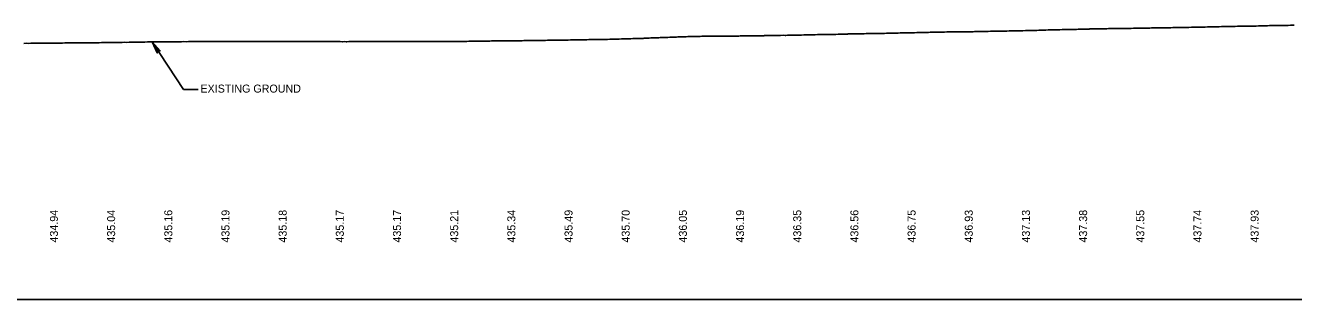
# Model space of a CAD drawing. Extents: x 2017200 to 2047700, y 854850 to 893350.
# Drawn here: x 2021520 to 2022630, y 856100 to 856340 of the extents above; entities that cross this region are included whole.
import ezdxf

# ---------------------------------------------------------------- set-up
doc = ezdxf.new("R2010")
doc.units = 0
for name, color, linetype in [('RD_DDB_Profile_EX', 7, 'Continuous'), ('RD_DDB_Profile_Lbl', 7, 'Continuous'), ('RD_DDB_StripGrade', 7, 'Continuous'), ('RD_GPK_Profile_Cell', 7, 'Continuous')]:
    doc.layers.add(name, color=color, linetype=linetype)

msp = doc.modelspace()

# ---------------------------------------------------------------- linework, layer by layer
at = {"layer": 'RD_DDB_Profile_EX'}
msp.add_lwpolyline([(2021519.1, 856324.3), (2021521.2, 856324.5), (2021523.1, 856324.4), (2021525.3, 856324.5), (2021527.1, 856324.5), (2021529.1, 856324.5), (2021531.1, 856324.5), (2021533.1, 856324.5), (2021533.7, 856324.5), (2021535.1, 856324.6), (2021537.1, 856324.5), (2021539.1, 856324.6), (2021541.1, 856324.6), (2021543.1, 856324.6), (2021545.1, 856324.6), (2021547.2, 856324.7), (2021549.1, 856324.7), (2021551.1, 856324.7), (2021553.1, 856324.7), (2021555.1, 856324.8), (2021555.7, 856324.8), (2021557.1, 856324.8), (2021559.1, 856324.8), (2021561.1, 856324.8), (2021563.1, 856324.9), (2021565.1, 856324.9), (2021567.2, 856324.9), (2021569.1, 856324.9), (2021571.1, 856324.9), (2021573.1, 856324.9), (2021573.9, 856324.9), (2021575.1, 856324.9), (2021577.1, 856325), (2021579.1, 856325), (2021581.1, 856325), (2021583.1, 856325), (2021585.1, 856325), (2021587.1, 856325.1), (2021589.1, 856325.1), (2021591.1, 856325.1), (2021593.1, 856325.1), (2021595.1, 856325.1), (2021597.1, 856325.2), (2021599.1, 856325.2), (2021600.2, 856325.2), (2021601.1, 856325.2), (2021603.1, 856325.2), (2021605.1, 856325.2), (2021607.1, 856325.3), (2021609.1, 856325.2), (2021611.2, 856325.3), (2021613.1, 856325.3), (2021615.3, 856325.3), (2021617.1, 856325.4), (2021619.1, 856325.4), (2021621.3, 856325.5), (2021623.1, 856325.5), (2021625.1, 856325.5), (2021627.2, 856325.6), (2021629.1, 856325.6), (2021631.3, 856325.6), (2021633.2, 856325.7), (2021635.2, 856325.7), (2021637.3, 856325.7), (2021639.2, 856325.7), (2021641.2, 856325.7), (2021641.6, 856325.7), (2021643.1, 856325.8), (2021644.5, 856325.8), (2021645.1, 856325.8), (2021647.1, 856325.8), (2021647.5, 856325.8), (2021649.1, 856325.8), (2021651.1, 856325.8), (2021652.9, 856325.8), (2021653.2, 856325.8), (2021654.8, 856325.8), (2021655.2, 856325.8), (2021657.1, 856325.8), (2021659.2, 856325.9), (2021661.2, 856325.8), (2021663.3, 856325.9), (2021665.2, 856325.9), (2021667.1, 856325.9), (2021669.2, 856325.9), (2021671.1, 856325.9), (2021673.2, 856325.9), (2021675.1, 856325.9), (2021677.1, 856325.9), (2021679.1, 856325.9), (2021681.1, 856325.9), (2021683.1, 856325.9), (2021683.6, 856325.9), (2021685.1, 856325.9), (2021687.1, 856325.9), (2021689.1, 856325.9), (2021691.1, 856326), (2021693.1, 856325.9), (2021695.1, 856325.9), (2021697.1, 856325.9), (2021698.4, 856325.9), (2021699.1, 856325.9), (2021701.1, 856325.9), (2021703.1, 856325.9), (2021705.1, 856326), (2021707.1, 856325.9), (2021709.1, 856325.9), (2021709.5, 856325.9), (2021711.1, 856325.9), (2021713.2, 856325.9), (2021715.2, 856325.9), (2021717.2, 856325.9), (2021719.1, 856325.9), (2021721.1, 856325.9), (2021723.2, 856325.9), (2021725.2, 856325.9), (2021726.7, 856325.9), (2021727.2, 856325.9), (2021729.3, 856325.9), (2021730.9, 856325.9), (2021731.2, 856325.9), (2021733.3, 856325.9), (2021735, 856325.9), (2021735.5, 856325.9), (2021736.8, 856325.9), (2021737.3, 856325.9), (2021739.1, 856325.9), (2021739.5, 856325.9), (2021741, 856325.9), (2021742.6, 856325.9), (2021743.4, 856325.9), (2021745.1, 856325.9), (2021746.8, 856325.9), (2021747.2, 856325.9), (2021749.2, 856325.9), (2021751.2, 856325.9), (2021752.7, 856325.9), (2021753.2, 856325.9), (2021755.2, 856325.9), (2021756.9, 856325.9), (2021757.2, 856325.9), (2021759.3, 856325.9), (2021761, 856325.9), (2021761.4, 856325.9), (2021763.3, 856325.9), (2021764.4, 856325.9), (2021765.1, 856325.9), (2021765.4, 856325.9), (2021767.1, 856325.9), (2021768.7, 856325.9), (2021769.5, 856325.9), (2021771.2, 856325.9), (2021771.8, 856325.9), (2021772.2, 856325.9), (2021773.2, 856325.9), (2021774.5, 856325.9), (2021775.3, 856325.9), (2021777.3, 856325.9), (2021778.9, 856325.9), (2021779.4, 856325.9), (2021780, 856325.9), (2021781.4, 856325.9), (2021783.1, 856325.9), (2021783.5, 856325.9), (2021784.8, 856325.9), (2021785.5, 856325.9), (2021787.2, 856325.9), (2021787.8, 856325.9), (2021789.2, 856325.9), (2021789.5, 856325.9), (2021791.6, 856325.9), (2021793.3, 856325.9), (2021793.9, 856325.9), (2021795.7, 856325.9), (2021797.4, 856325.8), (2021797.8, 856325.8), (2021799.4, 856325.9), (2021801, 856325.8), (2021801.5, 856325.8), (2021803.5, 856325.9), (2021805.6, 856325.9), (2021807, 856325.9), (2021807.6, 856325.9), (2021809.6, 856325.9), (2021811.3, 856325.9), (2021811.6, 856325.9), (2021813.7, 856325.9), (2021815.7, 856325.9), (2021817.7, 856325.9), (2021819, 856325.9), (2021819.8, 856325.9), (2021821.7, 856325.9), (2021823.8, 856325.9), (2021825.7, 856325.9), (2021826.8, 856325.9), (2021827.7, 856325.9), (2021829.7, 856325.9), (2021831.7, 856325.9), (2021833.8, 856325.9), (2021834.6, 856325.9), (2021835.3, 856325.9), (2021835.8, 856325.9), (2021837.8, 856325.9), (2021839.9, 856325.9), (2021841.8, 856325.9), (2021842.4, 856325.9), (2021843.9, 856325.9), (2021845.9, 856325.9), (2021847.9, 856325.9), (2021850.2, 856325.9), (2021852, 856325.9), (2021854, 856325.9), (2021856.1, 856325.9), (2021858, 856325.9), (2021860, 856325.9), (2021862.1, 856325.9), (2021864, 856325.9), (2021864.8, 856325.9), (2021866.1, 856325.9), (2021868.1, 856325.9), (2021870.2, 856325.9), (2021872.2, 856325.9), (2021873.6, 856325.9), (2021874.3, 856325.9), (2021876.3, 856325.9), (2021878.4, 856326), (2021880.1, 856326), (2021880.5, 856326), (2021881.4, 856326), (2021882.4, 856326), (2021884.5, 856326), (2021886.2, 856326), (2021888.3, 856326), (2021889.2, 856326), (2021890.3, 856326), (2021892.3, 856326), (2021894, 856326), (2021894.4, 856326), (2021896.4, 856326), (2021897, 856326), (2021898.5, 856326), (2021900, 856326.1), (2021900.5, 856326.1), (2021902.6, 856326.1), (2021904.8, 856326.1), (2021906.6, 856326.1), (2021908.4, 856326.2), (2021908.8, 856326.2), (2021910.3, 856326.2), (2021910.7, 856326.2), (2021912.8, 856326.2), (2021914.5, 856326.2), (2021915.3, 856326.2), (2021916.4, 856326.2), (2021917.5, 856326.2), (2021918.6, 856326.3), (2021919.1, 856326.3), (2021920.6, 856326.3), (2021922.1, 856326.3), (2021922.7, 856326.4), (2021924.7, 856326.4), (2021926.4, 856326.4), (2021926.8, 856326.4), (2021928.2, 856326.5), (2021928.8, 856326.5), (2021930.5, 856326.5), (2021930.8, 856326.5), (2021932.5, 856326.5), (2021932.8, 856326.5), (2021934.8, 856326.5), (2021936, 856326.6), (2021936.6, 856326.6), (2021937, 856326.6), (2021938.6, 856326.6), (2021938.9, 856326.6), (2021940.9, 856326.6), (2021942.7, 856326.6), (2021943.8, 856326.6), (2021944.9, 856326.6), (2021947, 856326.6), (2021948.8, 856326.7), (2021950.5, 856326.7), (2021950.9, 856326.7), (2021951.6, 856326.7), (2021952.9, 856326.7), (2021954.9, 856326.7), (2021956.5, 856326.8), (2021956.9, 856326.8), (2021959, 856326.8), (2021959.4, 856326.8), (2021960.7, 856326.9), (2021961, 856326.9), (2021963.1, 856326.9), (2021964.8, 856326.9), (2021965.2, 856326.9), (2021966.7, 856326.9), (2021967.2, 856326.9), (2021968.9, 856327), (2021969.3, 856327), (2021970.9, 856327), (2021971.5, 856327), (2021972.8, 856327), (2021973.3, 856327), (2021975, 856327), (2021975.5, 856327), (2021977, 856327.1), (2021978, 856327.1), (2021978.9, 856327.1), (2021980, 856327.1), (2021981.1, 856327.2), (2021983.2, 856327.2), (2021984.7, 856327.2), (2021985.2, 856327.2), (2021987.2, 856327.2), (2021989.3, 856327.3), (2021990.6, 856327.3), (2021991.3, 856327.3), (2021993.3, 856327.3), (2021995.3, 856327.3), (2021997.3, 856327.4), (2021998.4, 856327.4), (2021999.4, 856327.4), (2022001.4, 856327.5), (2022003.5, 856327.5), (2022005.3, 856327.5), (2022005.7, 856327.6), (2022006.2, 856327.6), (2022007.2, 856327.6), (2022008.7, 856327.6), (2022009.7, 856327.6), (2022011.4, 856327.6), (2022013.4, 856327.7), (2022014, 856327.7), (2022015.4, 856327.7), (2022017.5, 856327.8), (2022019.5, 856327.8), (2022021.5, 856327.8), (2022021.8, 856327.8), (2022022.8, 856327.9), (2022023.5, 856327.9), (2022025.7, 856327.9), (2022027.6, 856327.9), (2022029.6, 856327.9), (2022031.6, 856328), (2022033.7, 856328), (2022035.6, 856328.1), (2022037.6, 856328.1), (2022038, 856328.1), (2022039.4, 856328.2), (2022039.8, 856328.2), (2022041.7, 856328.3), (2022043.6, 856328.3), (2022044, 856328.3), (2022045.2, 856328.4), (2022045.8, 856328.4), (2022047.8, 856328.5), (2022049.7, 856328.5), (2022050, 856328.5), (2022051.7, 856328.6), (2022053, 856328.6), (2022053.3, 856328.6), (2022053.7, 856328.6), (2022054.7, 856328.6), (2022055.9, 856328.7), (2022057, 856328.7), (2022057.8, 856328.7), (2022059.4, 856328.7), (2022059.8, 856328.7), (2022060.8, 856328.8), (2022061.5, 856328.9), (2022062.1, 856328.9), (2022063.3, 856328.9), (2022064, 856329), (2022065.5, 856329), (2022065.9, 856329), (2022067.6, 856329.1), (2022068.2, 856329.1), (2022068.6, 856329.1), (2022069.5, 856329.2), (2022070.1, 856329.2), (2022071.6, 856329.3), (2022072, 856329.3), (2022073, 856329.3), (2022073.5, 856329.3), (2022074.4, 856329.3), (2022075.7, 856329.4), (2022076.4, 856329.4), (2022077.8, 856329.5), (2022078.1, 856329.5), (2022079, 856329.5), (2022079.8, 856329.5), (2022080.5, 856329.5), (2022081.9, 856329.6), (2022082.3, 856329.6), (2022084.2, 856329.7), (2022085, 856329.7), (2022086.1, 856329.8), (2022087.1, 856329.8), (2022088, 856329.8), (2022089.5, 856329.9), (2022090, 856329.9), (2022091, 856330), (2022092.2, 856330), (2022093.4, 856330.1), (2022094.2, 856330.1), (2022095.7, 856330.1), (2022096.1, 856330.1), (2022097.8, 856330.2), (2022098.4, 856330.2), (2022099.8, 856330.3), (2022100.3, 856330.3), (2022101.9, 856330.3), (2022102.3, 856330.3), (2022103, 856330.3), (2022103.6, 856330.4), (2022104.5, 856330.4), (2022105.9, 856330.4), (2022106.4, 856330.4), (2022107.6, 856330.5), (2022108, 856330.5), (2022108.4, 856330.5), (2022109.1, 856330.5), (2022109.9, 856330.5), (2022110.7, 856330.5), (2022112.1, 856330.6), (2022112.5, 856330.6), (2022114.1, 856330.6), (2022115.4, 856330.6), (2022116.2, 856330.6), (2022116.8, 856330.6), (2022118.2, 856330.6), (2022118.6, 856330.6), (2022120.3, 856330.6), (2022121.3, 856330.6), (2022122.4, 856330.6), (2022123.2, 856330.6), (2022123.5, 856330.6), (2022124.4, 856330.6), (2022125.8, 856330.7), (2022126.4, 856330.7), (2022127.4, 856330.7), (2022128.6, 856330.7), (2022129.8, 856330.7), (2022130.5, 856330.7), (2022131, 856330.7), (2022132, 856330.7), (2022132.5, 856330.7), (2022133.2, 856330.7), (2022133.5, 856330.7), (2022134.8, 856330.7), (2022136, 856330.8), (2022136.7, 856330.8), (2022138.2, 856330.8), (2022138.7, 856330.8), (2022139.3, 856330.8), (2022140, 856330.8), (2022140.9, 856330.8), (2022142.2, 856330.8), (2022142.8, 856330.8), (2022144.3, 856330.8), (2022145.5, 856330.9), (2022146.5, 856330.9), (2022147, 856330.9), (2022148.4, 856330.9), (2022148.9, 856330.9), (2022150.5, 856330.9), (2022151.6, 856331), (2022152.5, 856331), (2022153.1, 856331), (2022154.6, 856331), (2022155, 856331), (2022156.6, 856331), (2022157.6, 856331), (2022158.8, 856331), (2022160, 856331.1), (2022160.7, 856331.1), (2022162.3, 856331.1), (2022162.7, 856331.1), (2022164.5, 856331.1), (2022164.9, 856331.1), (2022166.3, 856331.1), (2022166.8, 856331.2), (2022168.8, 856331.2), (2022169.9, 856331.2), (2022170.6, 856331.2), (2022171, 856331.2), (2022172.5, 856331.2), (2022172.9, 856331.2), (2022174.9, 856331.3), (2022177, 856331.3), (2022177.7, 856331.3), (2022179, 856331.3), (2022180.9, 856331.4), (2022183.1, 856331.5), (2022185, 856331.4), (2022185.5, 856331.4), (2022187, 856331.5), (2022189.2, 856331.5), (2022191.1, 856331.6), (2022193.3, 856331.6), (2022195.3, 856331.6), (2022197, 856331.7), (2022199.1, 856331.7), (2022201.3, 856331.8), (2022203.1, 856331.8), (2022205.1, 856331.9), (2022206.2, 856331.9), (2022207.1, 856331.9), (2022209.2, 856332), (2022211.2, 856332), (2022213.3, 856332.1), (2022215.4, 856332.1), (2022216.7, 856332.1), (2022217.2, 856332.2), (2022219.4, 856332.2), (2022221.5, 856332.2), (2022223.3, 856332.2), (2022224.5, 856332.3), (2022225.3, 856332.3), (2022227.3, 856332.3), (2022229.4, 856332.3), (2022231.4, 856332.4), (2022232.3, 856332.4), (2022233.4, 856332.4), (2022235.4, 856332.5), (2022237.4, 856332.5), (2022239.4, 856332.5), (2022240.1, 856332.6), (2022241.5, 856332.6), (2022243.5, 856332.7), (2022245.6, 856332.7), (2022247.4, 856332.7), (2022247.9, 856332.7), (2022249.3, 856332.8), (2022249.7, 856332.8), (2022251.8, 856332.8), (2022253.5, 856332.8), (2022253.9, 856332.8), (2022255.7, 856332.9), (2022257.1, 856332.9), (2022257.8, 856332.9), (2022259.6, 856333), (2022260, 856333), (2022261.6, 856333), (2022263.7, 856333), (2022265.7, 856333), (2022267.7, 856333), (2022269.3, 856333.1), (2022269.7, 856333.1), (2022271.3, 856333.1), (2022271.7, 856333.1), (2022273.7, 856333.2), (2022275.7, 856333.2), (2022277.8, 856333.3), (2022279.1, 856333.3), (2022279.8, 856333.3), (2022281.8, 856333.4), (2022283.9, 856333.4), (2022285.6, 856333.5), (2022285.9, 856333.5), (2022286.9, 856333.5), (2022287.9, 856333.5), (2022290.2, 856333.6), (2022291.6, 856333.6), (2022292, 856333.6), (2022294, 856333.6), (2022294.7, 856333.7), (2022296, 856333.7), (2022296.3, 856333.7), (2022297.8, 856333.7), (2022298.1, 856333.7), (2022300.1, 856333.8), (2022302.1, 856333.8), (2022302.5, 856333.8), (2022304.2, 856333.9), (2022306.1, 856333.9), (2022308, 856334), (2022308.5, 856334), (2022310.3, 856334), (2022311.7, 856334.1), (2022312.1, 856334.1), (2022314.1, 856334.1), (2022316.3, 856334.1), (2022318.1, 856334.2), (2022320.2, 856334.2), (2022322.2, 856334.2), (2022324.2, 856334.3), (2022326.2, 856334.4), (2022328.2, 856334.4), (2022330.3, 856334.4), (2022332.3, 856334.4), (2022333.7, 856334.4), (2022334.3, 856334.4), (2022336.4, 856334.5), (2022338.4, 856334.5), (2022340.4, 856334.6), (2022341.5, 856334.6), (2022342.5, 856334.6), (2022344.5, 856334.6), (2022346.5, 856334.6), (2022348.7, 856334.6), (2022349.3, 856334.6), (2022350.4, 856334.7), (2022352.4, 856334.7), (2022354.7, 856334.8), (2022356.5, 856334.8), (2022357.1, 856334.8), (2022358.5, 856334.8), (2022360.5, 856334.8), (2022362.6, 856334.9), (2022364.6, 856335), (2022364.9, 856335), (2022366.6, 856335), (2022368.7, 856335), (2022370.6, 856335.1), (2022372.7, 856335.1), (2022374.7, 856335.2), (2022376.7, 856335.2), (2022378.7, 856335.2), (2022380.7, 856335.3), (2022382.8, 856335.3), (2022384.8, 856335.3), (2022386.8, 856335.4), (2022388.3, 856335.4), (2022388.9, 856335.4), (2022390.9, 856335.5), (2022392.9, 856335.5), (2022395, 856335.6), (2022396.1, 856335.6), (2022396.8, 856335.6), (2022398.9, 856335.7), (2022400.9, 856335.7), (2022402.9, 856335.7), (2022403.9, 856335.8), (2022404.9, 856335.8), (2022406.9, 856335.9), (2022409, 856335.9), (2022411, 856336), (2022411.7, 856336), (2022413, 856336), (2022415, 856336.1), (2022417.1, 856336.1), (2022419.1, 856336.2), (2022419.5, 856336.2), (2022421.1, 856336.2), (2022423.2, 856336.3), (2022425.2, 856336.3), (2022427.3, 856336.4), (2022429.1, 856336.4), (2022429.4, 856336.4), (2022431.3, 856336.5), (2022433.2, 856336.5), (2022435.4, 856336.6), (2022437.2, 856336.6), (2022439.2, 856336.6), (2022439.6, 856336.6), (2022441.2, 856336.7), (2022442.9, 856336.8), (2022443.3, 856336.8), (2022445.3, 856336.8), (2022447.3, 856336.9), (2022449.4, 856336.9), (2022450.7, 856336.9), (2022451.4, 856337), (2022453.5, 856337), (2022455.4, 856337), (2022457.4, 856337), (2022458.4, 856337.1), (2022459.4, 856337.1), (2022461.4, 856337.1), (2022463.6, 856337.2), (2022465.6, 856337.2), (2022466.3, 856337.2), (2022467.6, 856337.3), (2022469.6, 856337.3), (2022470, 856337.3), (2022471.3, 856337.3), (2022471.8, 856337.3), (2022473.7, 856337.3), (2022474.1, 856337.3), (2022475.6, 856337.4), (2022477.5, 856337.4), (2022477.9, 856337.4), (2022479.8, 856337.4), (2022481.9, 856337.5), (2022483.6, 856337.5), (2022484, 856337.5), (2022485.6, 856337.5), (2022487.3, 856337.5), (2022487.6, 856337.5), (2022489.7, 856337.6), (2022492, 856337.6), (2022493.7, 856337.7), (2022495.7, 856337.7), (2022497.8, 856337.7), (2022499.9, 856337.7), (2022501.5, 856337.8), (2022501.8, 856337.8), (2022503.8, 856337.8), (2022505.3, 856337.9), (2022505.7, 856337.9), (2022506, 856337.9), (2022507.6, 856337.9), (2022508, 856337.9), (2022509.9, 856338), (2022511.9, 856337.9), (2022512.3, 856338), (2022513.1, 856338), (2022513.6, 856338), (2022514.1, 856338), (2022516, 856338), (2022518, 856338.1), (2022520.1, 856338.1), (2022520.9, 856338.1), (2022522.1, 856338.1), (2022524, 856338.2), (2022526.2, 856338.2), (2022528.1, 856338.3), (2022528.7, 856338.3), (2022530.1, 856338.3), (2022532.1, 856338.4), (2022534.1, 856338.4), (2022536.1, 856338.4), (2022536.5, 856338.4), (2022538.1, 856338.4), (2022540.2, 856338.5), (2022542.2, 856338.6), (2022544.3, 856338.6), (2022546.2, 856338.6), (2022548.2, 856338.6), (2022550.2, 856338.7), (2022552.3, 856338.7), (2022554.3, 856338.8), (2022556.3, 856338.8), (2022558.3, 856338.9), (2022559.9, 856338.9), (2022560.3, 856338.9), (2022562.3, 856339), (2022563.9, 856339), (2022564.4, 856339), (2022566.4, 856339.1), (2022567.7, 856339.1), (2022568.4, 856339.1), (2022570.5, 856339.2), (2022572.6, 856339.2), (2022574.4, 856339.3), (2022575.5, 856339.3), (2022576.5, 856339.3), (2022578.5, 856339.3), (2022580.5, 856339.4), (2022582.5, 856339.4), (2022583.3, 856339.4), (2022584.6, 856339.4), (2022586.6, 856339.5), (2022588.6, 856339.5), (2022590.6, 856339.5), (2022591.1, 856339.5), (2022592.7, 856339.5), (2022594.7, 856339.5), (2022596.7, 856339.5), (2022598.9, 856339.6), (2022599.5, 856339.6), (2022600.7, 856339.7), (2022602.7, 856339.7), (2022604.7, 856339.8), (2022606.9, 856339.8), (2022608.5, 856339.9), (2022608.9, 856339.9), (2022610.9, 856339.9), (2022612.9, 856339.9), (2022614.7, 856340), (2022615, 856340), (2022617, 856340), (2022618.9, 856340), (2022621.2, 856340.1), (2022622.3, 856340.1), (2022623, 856340.1), (2022624.9, 856340.1), (2022626.9, 856340.2), (2022629.2, 856340.2), (2022630.1, 856340.2)], dxfattribs=at)
at = {"layer": 'RD_DDB_Profile_Lbl'}
for p, q in [((2021658.8, 856283.9), (2021631.3, 856325.6)), ((2021671.7, 856283.9), (2021658.8, 856283.9))]:
    msp.add_line(p, q, dxfattribs=at)
msp.add_lwpolyline([(2021631.3, 856325.6), (2021635.8, 856316.1), (2021636.2, 856318.3), (2021638.3, 856317.8)], close=True, dxfattribs=at)
at = {"layer": 'RD_GPK_Profile_Cell'}
msp.add_line((2020500, 856100), (2047700, 856100), dxfattribs=at)

# ---------------------------------------------------------------- texts
at = {"layer": 'RD_DDB_Profile_Lbl'}
msp.add_text('EXISTING GROUND', height=7, dxfattribs=at).set_placement((2021673.6, 856281.3))
at = {"layer": 'RD_DDB_StripGrade'}
for s, p in [('434.94', (2021549, 856150)), ('435.04', (2021599, 856150)), ('435.16', (2021649, 856150)), ('435.19', (2021699, 856150)), ('435.18', (2021749, 856150)), ('435.17', (2021799, 856150)), ('435.17', (2021849, 856150)), ('435.21', (2021899, 856150)), ('435.34', (2021949, 856150)), ('435.49', (2021999, 856150)), ('435.70', (2022049, 856150)), ('436.05', (2022099, 856150)), ('436.19', (2022149, 856150)), ('436.35', (2022199, 856150)), ('436.56', (2022249, 856150)), ('436.75', (2022299, 856150)), ('436.93', (2022349, 856150)), ('437.13', (2022399, 856150)), ('437.38', (2022449, 856150)), ('437.55', (2022499, 856150)), ('437.74', (2022549, 856150)), ('437.93', (2022599, 856150))]:
    msp.add_text(s, height=7, rotation=90, dxfattribs=at).set_placement(p)

doc.saveas('drawing.dxf')
